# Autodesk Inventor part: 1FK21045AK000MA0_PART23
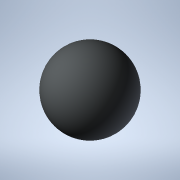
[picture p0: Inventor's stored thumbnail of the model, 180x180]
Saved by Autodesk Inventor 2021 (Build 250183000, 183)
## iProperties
Created: 2025-04
Part Number: 1FK21045AK000MA0_PART23
Material: Generic
Catalog Web Link: www.3dfindit.com
Description: -Servo synchronous motor
Document SubType Name: Modeling
Designer: psAdmin
Mass: 0.137258 g
Surface Area: 1.2868 cm^2
Volume: 0.137258 cm^3
Density: 1 g/cm^3
Appearance: PSOLRGB-212-217-219
Category: PARTsolutions
Title: 1FK21045AK000MA0_PART23
Author: Cadenas PARTsolutions
Comments: Servo synchronous motor
Sending System: PARTsolutions
Preprocessor: ST-DEVELOPER v19.3
PSOL_IDENT_0: {$CADENAS_DATA/23d-libs/siemens_ag/_cat_/3d/2f/1fk21045ak000ma0.prj},216 {VTYP=3D},{NB=1FK21045AK000
PSOL_IDENT_1: MA0_PART23},{LINA=1FK21045AK000MA0_PART23},{NN=1FK21045AK000MA0_PART23},{NOPRJ=TRUE},{DATE=19.08.202
PSOL_IDENT_2: 5 14:00:34},{GEOMDATE=30.07.2025 02:01:24},{VERSION=},{LINEID=10},{WBVAR=},{WBNUMERIC=}  {NB=1FK2104
PSOL_IDENT_3: 5AK000MA0_PART23},{LINA=1FK21045AK000MA0_PART23},{KT=DUMMY},{PREVIEW=../../../_pool_/a9/69/p_d211_xx
PSOL_IDENT_4: _00818j.png},{DESCSHORT=SIMOTICS S-1FK2 HD, SINAMICS S210 3AC 400V-480V, 1.7 Nm, 6000 rpm},{DESCLONG=
PSOL_IDENT_5: SIMOTICS S-1FK2 HD servo motor M0=2.4 Nm; PN = 1.07 kW at nN=6000 rpm (380-480 V); PN = 0.75 kW at n
PSOL_IDENT_6: N=3000 rpm (200-240 V); degree of protection IP64; cylindrical shaft D19x40mm; absolute encoder 22-b
PSOL_IDENT_7: it + 12-bit multiturn (encoder AM22DQC); with OCC interface; plug size M17, rotatable; SIMOTICS S-1F
PSOL_IDENT_8: K2 servomotorfor a wide range of uses in industrial environments. SIMOTICS S‑1FK2 servomotors are co
PSOL_IDENT_9: mpact synchronous motors with a high dynamic performance that set themselves apart as a result of th
PSOL_IDENT_10: eir high power density, degree of protection and overload capability. The motors are available in tw
PSOL_IDENT_11: o variants: as High Dynamic variant (highest dynamic performance as a result of the low intrinsic mo
PSOL_IDENT_12: ment of inertia for applications demanding a high dynamic performance with low moved masses) - and a
PSOL_IDENT_13: s Compact variant (precise and stable closed-loop control for medium up to large moved masses as a r
PSOL_IDENT_14: esult of a medium intrinsic moment of inertia). SIMOTICSS‑1FK2 servomotors fully exploit their stren
PSOL_IDENT_15: gths in a system with the SINAMICSS210 frequency converter and simple connection using the one cable
PSOL_IDENT_16: connection (OCC). Advantages include the short control and positioning times, fast and precise corr
PSOL_IDENT_17: ection of disturbing quantities as well as stable control with a high dynamic performance. The servo
PSOL_IDENT_18: motors can be configured to address a wide range of requirements. For example with and without hold
PSOL_IDENT_19: ing brake, IP64 or IP65 degree of protection, singleturn or multiturn absolute encoders - to name ju
PSOL_IDENT_20: st a few. Further, the servomotors are available in different shaft heights extending from 20 to 100
PSOL_IDENT_21: . A shaft sealing ring is available to achieve an IP65 degree of protection and for subsequent mount
PSOL_IDENT_22: ing at the motor or as spare part. SIMOTICS - the optimum motor for each and every motion control ap
PSOL_IDENT_23: plication.},{INTNO=804766789342},{SUPPLIERALTNO=1FK2104-5AK00-0MA0},{MANUID=1FK21045AK000MA0},{MANUN
PSOL_IDENT_24: AME=Siemens},{MANUTYPEDESC=Synchronous motor 1FK2-HD 2,39 Nm},{AAU732=SIMOTICS},{AAO057=S-1FK2},{AAU
PSOL_IDENT_25: 734=SIMOTICS S-1FK2 HD servo motor M0=2.4 Nm; PN = 1.07 kW at nN=6000 rpm (380-480 V); PN = 0.75 kW
PSOL_IDENT_26: at nN=3000 rpm (200-240 V); degree of protection IP64; cylindrical shaft D19x40mm; absolute encoder
PSOL_IDENT_27: 22-bit + 12-bit multiturn (encoder AM22DQC); with OCC interface; plug size M17, rotatable;},{AAW338=
PSOL_IDENT_28: Synchronous motor 1FK2-HD 2,39 Nm},{AAO742=SIMOTICS},{AAO663=4042948691151},{NOCUPEROU=1},{PRICEQUAN
PSOL_IDENT_29: TITY=1},{QUANTITYMIN=1},{QUANTITYINT=1},{CTN=85015100},{COO=DE},{AAO676=1FK2104-5AK00-0MA0},{AAO677=
PSOL_IDENT_30: Siemens AG},{ORDERUNIT=C62},{CONTENTUNIT=C62}
NB: 1FK21045AK000MA0_PART23
NT: Servo synchronous motor
NBSYN: $MANUID._PART23
LINA: 1FK21045AK000MA0_PART23
CATALOG: SIEMENS
PREVIEW: ../../../_pool_/a9/69/p_d211_xx_00818j.png
DESCSHORT: SIMOTICS S-1FK2 HD, SINAMICS S210 3AC 400V-480V, 1.7 Nm, 6000 rpm
DESCLONG: SIMOTICS S-1FK2 HD servo motor M0=2.4 Nm; PN = 1.07 kW at nN=6000 rpm (380-480 V); PN = 0.75 kW at nN=3000 rpm (200-240 V); degree of protection IP64; cylindric
INTNO: 804766789342
SUPPLIERALTNO: 1FK2104-5AK00-0MA0
MANUID: 1FK21045AK000MA0
MANUNAME: Siemens
MANUTYPEDESC: Synchronous motor 1FK2-HD 2,39 Nm
AAU732: SIMOTICS
AAO057: S-1FK2
AAU734: SIMOTICS S-1FK2 HD servo motor M0=2.4 Nm; PN = 1.07 kW at nN=6000 rpm (380-480 V); PN = 0.75 kW at nN=3000 rpm (200-240 V); degree of protection IP64; cylindric
AAW338: Synchronous motor 1FK2-HD 2,39 Nm
AAO742: SIMOTICS
AAO663: 4042948691151.0
NOCUPEROU: 1
PRICEQUANTITY: 1
QUANTITYMIN: 1
QUANTITYINT: 1
CTN: 85015100
COO: DE
ARTICLENO: 1FK21045AK000MA0_PART23
BOMINFO: 1FK21045AK000MA0_PART23
CREATOR: CADENAS GmbH
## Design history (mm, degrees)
feature "2025_04_17_15_39_51_0728"
body "Solid1"
